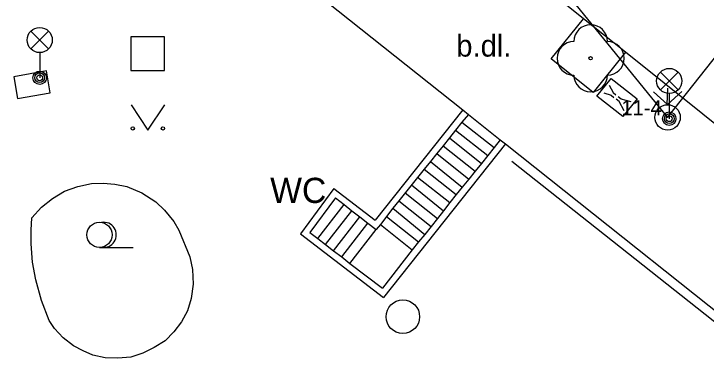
# Model space of a CAD drawing. Extents: x -598168 to -598014, y -1160410 to -1160294.
# Drawn here: x -598070.05 to -598049.44, y -1160393.71 to -1160383.46 of the extents above; entities that cross this region are included whole.
import ezdxf

# ---------------------------------------------------------------- set-up
doc = ezdxf.new("R2010")
doc.units = 0
for name, color, linetype in [('Level 10', 7, 'Continuous'), ('Level 11', 7, 'Continuous'), ('Level 21', 7, 'Continuous'), ('Level 22', 7, 'Continuous'), ('Level 26', 7, 'Continuous'), ('Level 27', 7, 'Continuous'), ('Level 33', 7, 'Continuous'), ('Level 36', 7, 'Continuous'), ('Level 40', 7, 'Continuous'), ('Level 41', 7, 'Continuous'), ('Level 9', 7, 'Continuous'), ('Trolejové vedení_Kotvení', 7, 'Continuous'), ('Trolejové vedení_Nosné lano', 7, 'Continuous'), ('Trolejové vedení_Stožáry', 7, 'Continuous')]:
    doc.layers.add(name, color=color, linetype=linetype)

# ---------------------------------------------------------------- blocks, each defined once
blk = doc.blocks.new('TRAKCN')
at = {"layer": 'Trolejové vedení_Stožáry'}
for points in [[(-0.0008, 0.0382), (0.0004, 0.0868)], [(0, 0.0382), (-0.042, 0.0763)], [(0, 0.0386), (0.0421, 0.0768)]]:
    blk.add_lwpolyline(points, dxfattribs=at)
blk.add_circle((0, 0), 0.0378, dxfattribs=at)
blk = doc.blocks.new('KOTVEN')
at = {"layer": 'Trolejové vedení_Kotvení'}
blk.add_lwpolyline([(-0.0343, 0.0522), (0.0333, 0.0522), (0.0338, -0.0458), (-0.0343, -0.0455)], close=True, dxfattribs=at)
for points in [[(-0.0158, 0.0443), (-0.0041, 0.0154), (-0.004, 0.0041)], [(0.0172, 0.0445), (0.005, 0.0158), (0.005, 0.0039)], [(-0.0145, -0.0376), (-0.0045, -0.015), (-0.0045, -0.004)], [(0.0131, -0.0362), (0.0052, -0.0148), (0.0051, -0.004)]]:
    blk.add_lwpolyline(points, dxfattribs=at)

msp = doc.modelspace()

# ---------------------------------------------------------------- linework, layer by layer
at = {"layer": 'Level 10'}
for points in [[(-598053.09, -1160383.6), (-598055.57, -1160381.6)], [(-598051.84, -1160384.6), (-598053.09, -1160383.6)], [(-598048.39, -1160387.37), (-598051.84, -1160384.6)]]:
    msp.add_lwpolyline(points, dxfattribs=at)
at = {"layer": 'Level 11'}
for points in [[(-598067.53, -1160377.69), (-598056.68, -1160386.32)], [(-598051.84, -1160384.6), (-598052.8, -1160385.8), (-598054.06, -1160384.8), (-598053.09, -1160383.6)], [(-598069.08, -1160385.15), (-598070.05, -1160385.33)], [(-598068.97, -1160385.81), (-598069.08, -1160385.15)], [(-598070.05, -1160385.33), (-598069.94, -1160385.98)], [(-598069.94, -1160385.98), (-598068.97, -1160385.81)], [(-598056.68, -1160386.32), (-598059.29, -1160389.6)], [(-598056.68, -1160386.32), (-598056.52, -1160386.45)], [(-598056.52, -1160386.45), (-598056.71, -1160386.68)], [(-598056.52, -1160386.45), (-598055.57, -1160387.21)], [(-598056.71, -1160386.68), (-598056.9, -1160386.92)], [(-598056.71, -1160386.68), (-598055.75, -1160387.44)], [(-598056.9, -1160386.92), (-598057.08, -1160387.15)], [(-598056.9, -1160386.92), (-598055.94, -1160387.68)], [(-598057.08, -1160387.15), (-598057.27, -1160387.39)], [(-598057.08, -1160387.15), (-598056.13, -1160387.91)], [(-598055.41, -1160387.33), (-598059.05, -1160391.91)], [(-598055.57, -1160387.21), (-598055.75, -1160387.44)], [(-598055.57, -1160387.21), (-598055.41, -1160387.33)], [(-598055.41, -1160387.33), (-598046.73, -1160394.24), (-598040.975, -1160398.804)], [(-598057.27, -1160387.39), (-598057.46, -1160387.62)], [(-598057.27, -1160387.39), (-598056.32, -1160388.14)], [(-598055.75, -1160387.44), (-598055.94, -1160387.68)], [(-598057.46, -1160387.62), (-598057.65, -1160387.85)], [(-598057.46, -1160387.62), (-598056.51, -1160388.38)], [(-598055.94, -1160387.68), (-598056.13, -1160387.91)], [(-598057.65, -1160387.85), (-598057.84, -1160388.08)], [(-598057.65, -1160387.85), (-598056.7, -1160388.62)], [(-598056.13, -1160387.91), (-598056.32, -1160388.14)], [(-598057.84, -1160388.08), (-598058.59, -1160389.03)], [(-598057.84, -1160388.08), (-598056.88, -1160388.84)], [(-598056.32, -1160388.14), (-598056.51, -1160388.38)], [(-598058.03, -1160388.32), (-598057.07, -1160389.08)], [(-598056.51, -1160388.38), (-598056.7, -1160388.62)], [(-598058.21, -1160388.55), (-598057.26, -1160389.32)], [(-598060.52, -1160388.66), (-598061.52, -1160390.01)], [(-598060.52, -1160388.66), (-598059.29, -1160389.6)], [(-598058.4, -1160388.79), (-598057.44, -1160389.55)], [(-598056.7, -1160388.62), (-598056.88, -1160388.84)], [(-598060.48, -1160388.94), (-598061.24, -1160389.97)], [(-598060.48, -1160388.94), (-598060.22, -1160389.14)], [(-598056.88, -1160388.84), (-598057.07, -1160389.08)], [(-598061, -1160390.15), (-598060.22, -1160389.14)], [(-598060.22, -1160389.14), (-598059.99, -1160389.32)], [(-598058.59, -1160389.03), (-598058.77, -1160389.25)], [(-598058.59, -1160389.03), (-598057.63, -1160389.79)], [(-598057.07, -1160389.08), (-598057.26, -1160389.32)], [(-598060.77, -1160390.33), (-598059.99, -1160389.32)], [(-598059.99, -1160389.32), (-598059.75, -1160389.5)], [(-598058.77, -1160389.25), (-598059.14, -1160389.73)], [(-598058.77, -1160389.25), (-598057.82, -1160390.03)], [(-598057.26, -1160389.32), (-598057.44, -1160389.55)], [(-598060.53, -1160390.52), (-598059.75, -1160389.5)], [(-598059.75, -1160389.5), (-598059.51, -1160389.69)], [(-598058.96, -1160389.49), (-598058, -1160390.25)], [(-598057.44, -1160389.55), (-598057.63, -1160389.79)], [(-598060.29, -1160390.7), (-598059.51, -1160389.69)], [(-598059.51, -1160389.69), (-598059.26, -1160389.88)], [(-598059.14, -1160389.73), (-598059.26, -1160389.88)], [(-598059.14, -1160389.73), (-598058.19, -1160390.49)], [(-598057.63, -1160389.79), (-598057.82, -1160390.03)], [(-598061.52, -1160390.01), (-598059.05, -1160391.91)], [(-598061.24, -1160389.97), (-598061, -1160390.15)], [(-598060.05, -1160390.89), (-598059.26, -1160389.88)], [(-598057.82, -1160390.03), (-598058, -1160390.25)], [(-598061, -1160390.15), (-598060.77, -1160390.33)], [(-598060.77, -1160390.33), (-598060.53, -1160390.52)], [(-598058, -1160390.25), (-598058.19, -1160390.49)], [(-598060.53, -1160390.52), (-598060.29, -1160390.7)], [(-598058.19, -1160390.49), (-598059.08, -1160391.63)], [(-598060.29, -1160390.7), (-598060.05, -1160390.89)], [(-598060.05, -1160390.89), (-598059.08, -1160391.63)]]:
    msp.add_lwpolyline(points, dxfattribs=at)
at = {"layer": 'Level 21'}
for points in [[(-598068.15, -1160388.6), (-598067.74, -1160388.51)], [(-598067.74, -1160388.51), (-598067.39, -1160388.5)], [(-598067.39, -1160388.5), (-598067.04, -1160388.53)], [(-598067.04, -1160388.53), (-598066.69, -1160388.6)], [(-598068.9, -1160388.96), (-598068.54, -1160388.74)], [(-598068.54, -1160388.74), (-598068.15, -1160388.6)], [(-598066.69, -1160388.6), (-598066.24, -1160388.79)], [(-598066.24, -1160388.79), (-598065.82, -1160389.06)], [(-598069.23, -1160389.22), (-598068.9, -1160388.96)], [(-598065.82, -1160389.06), (-598065.57, -1160389.3)], [(-598069.51, -1160389.53), (-598069.23, -1160389.22)], [(-598065.57, -1160389.3), (-598065.29, -1160389.64)], [(-598069.53, -1160389.9), (-598069.51, -1160389.53)], [(-598065.29, -1160389.64), (-598065.14, -1160389.9)], [(-598069.53, -1160390.31), (-598069.53, -1160389.9)], [(-598065.14, -1160389.9), (-598064.81, -1160390.7)], [(-598069.49, -1160390.85), (-598069.53, -1160390.31)], [(-598069.4, -1160391.38), (-598069.49, -1160390.85)], [(-598064.81, -1160390.7), (-598064.73, -1160391.07)], [(-598064.73, -1160391.07), (-598064.71, -1160391.51)], [(-598069.23, -1160392), (-598069.4, -1160391.38)], [(-598064.71, -1160391.51), (-598064.77, -1160391.94)], [(-598069, -1160392.59), (-598069.23, -1160392)], [(-598064.77, -1160391.94), (-598064.88, -1160392.3)], [(-598064.88, -1160392.3), (-598065.06, -1160392.63)], [(-598068.84, -1160392.83), (-598069, -1160392.59)], [(-598065.06, -1160392.63), (-598065.29, -1160392.93)], [(-598068.58, -1160393.11), (-598068.84, -1160392.83)], [(-598068.27, -1160393.35), (-598068.58, -1160393.11)], [(-598065.29, -1160392.93), (-598065.55, -1160393.2)], [(-598065.55, -1160393.2), (-598065.87, -1160393.4)], [(-598067.99, -1160393.5), (-598068.27, -1160393.35)], [(-598067.7, -1160393.62), (-598067.99, -1160393.5)], [(-598065.87, -1160393.4), (-598066.21, -1160393.57)], [(-598067.33, -1160393.7), (-598067.7, -1160393.62)], [(-598066.95, -1160393.71), (-598067.33, -1160393.7)], [(-598066.57, -1160393.68), (-598066.95, -1160393.71)], [(-598066.21, -1160393.57), (-598066.57, -1160393.68)]]:
    msp.add_lwpolyline(points, dxfattribs=at)
at = {"layer": 'Level 22'}
msp.add_circle((-598052.88, -1160384.78), 0.05, dxfattribs=at)
for centre, start, end in [((-598052.88, -1160384.28), 0, 180), ((-598053.38, -1160384.78), 90, 270), ((-598052.38, -1160384.78), 270, 90), ((-598052.88, -1160385.28), 180, 0)]:
    msp.add_arc(centre, 0.5, start, end, dxfattribs=at)
at = {"layer": 'Level 26'}
msp.add_lwpolyline([(-598066.57, -1160385.14), (-598065.57, -1160385.14), (-598065.57, -1160384.14), (-598066.57, -1160384.14)], close=True, dxfattribs=at)
at = {"layer": 'Level 27'}
msp.add_circle((-598058.47, -1160392.48), 0.5, dxfattribs=at)
at = {"layer": 'Level 33'}
for p, q in [((-598069.545, -1160384.5), (-598069.015, -1160383.97)), ((-598069.545, -1160383.97), (-598069.015, -1160384.5)), ((-598069.28, -1160384.61), (-598069.28, -1160385.36)), ((-598050.805, -1160385.72), (-598050.275, -1160385.19)), ((-598050.805, -1160385.19), (-598050.275, -1160385.72)), ((-598050.54, -1160385.83), (-598050.54, -1160386.58))]:
    msp.add_line(p, q, dxfattribs=at)
for centre, radius in [((-598069.28, -1160384.235), 0.375), ((-598050.54, -1160385.455), 0.375), ((-598069.28, -1160385.36), 0.2), ((-598069.28, -1160385.36), 0.145), ((-598069.28, -1160385.36), 0.0876), ((-598050.54, -1160386.58), 0.2), ((-598050.54, -1160386.58), 0.145), ((-598050.54, -1160386.58), 0.0876)]:
    msp.add_circle(centre, radius, dxfattribs=at)
at = {"layer": 'Level 36'}
msp.add_line((-598067.5, -1160390.415), (-598066.5, -1160390.415), dxfattribs=at)
msp.add_lwpolyline([(-598066.56, -1160386.17), (-598066.06, -1160386.92), (-598065.56, -1160386.17)], dxfattribs=at)
for centre, radius in [((-598066.51, -1160386.87), 0.05), ((-598065.611, -1160386.87), 0.05), ((-598067.5, -1160390.04), 0.375)]:
    msp.add_circle(centre, radius, dxfattribs=at)
msp.add_arc((-598067.375, -1160390.04), 0.375, 260.4059, 99.5941, dxfattribs=at)
at = {"layer": 'Level 9'}
msp.add_lwpolyline([(-598055.23, -1160387.84), (-598041.191, -1160398.959)], dxfattribs=at)
at = {"layer": 'Trolejové vedení_Nosné lano'}
for points in [[(-598050.59, -1160386.54), (-598037.79, -1160370.36)], [(-598050.59, -1160386.54), (-598037.79, -1160370.36)], [(-598062.15, -1160372.31), (-598050.59, -1160386.54)], [(-598062.15, -1160372.31), (-598050.59, -1160386.54)]]:
    msp.add_lwpolyline(points, dxfattribs=at)

# ---------------------------------------------------------------- block references
at = {"layer": 'Trolejové vedení_Kotvení', "xscale": 10, "yscale": 10, "rotation": -128.22247193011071}
msp.add_blockref('KOTVEN', (-598052.122, -1160385.931), dxfattribs=at)
at = {"layer": 'Trolejové vedení_Stožáry', "xscale": 10, "yscale": 10}
msp.add_blockref('TRAKCN', (-598050.59, -1160386.54), dxfattribs=at)

# ---------------------------------------------------------------- texts
at = {"layer": 'Level 40'}
msp.add_text('b.dl.', height=0.65, dxfattribs=at).set_placement((-598056.88, -1160384.73))
at = {"layer": 'Level 41'}
msp.add_text('WC', height=0.75, dxfattribs=at).set_placement((-598062.42, -1160389.09))
at = {"layer": 'Trolejové vedení_Stožáry'}
msp.add_text('11-4', height=0.45, dxfattribs=at).set_placement((-598051.967, -1160386.48))

doc.saveas('drawing.dxf')
